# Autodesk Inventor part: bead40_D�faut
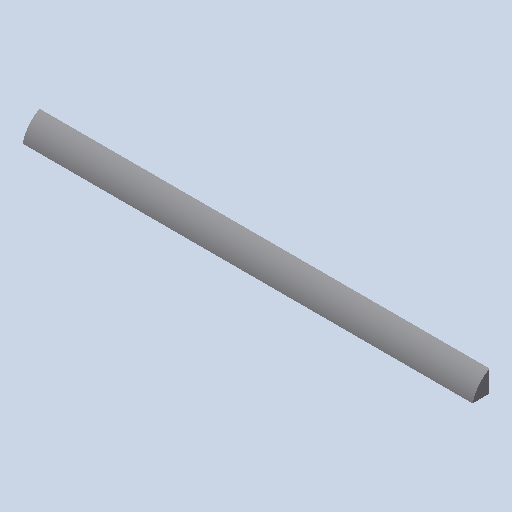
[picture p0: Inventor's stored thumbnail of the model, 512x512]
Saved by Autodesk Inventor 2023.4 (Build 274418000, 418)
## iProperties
Created: 2011-01
Part Number: bead40_D�faut
Document SubType Name: Modeling
Designer: eric
Density: 1 g/cm^3
Mass: 0.07456 g
Surface Area: 2.41867 cm^2
Volume: 0.07456 cm^3
Material: Générique
Appearance: Par défaut
Author: eric
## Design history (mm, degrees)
feature "Base1"
node "Corps solides"
node "Corps surfaciques"
node "Solide1"
